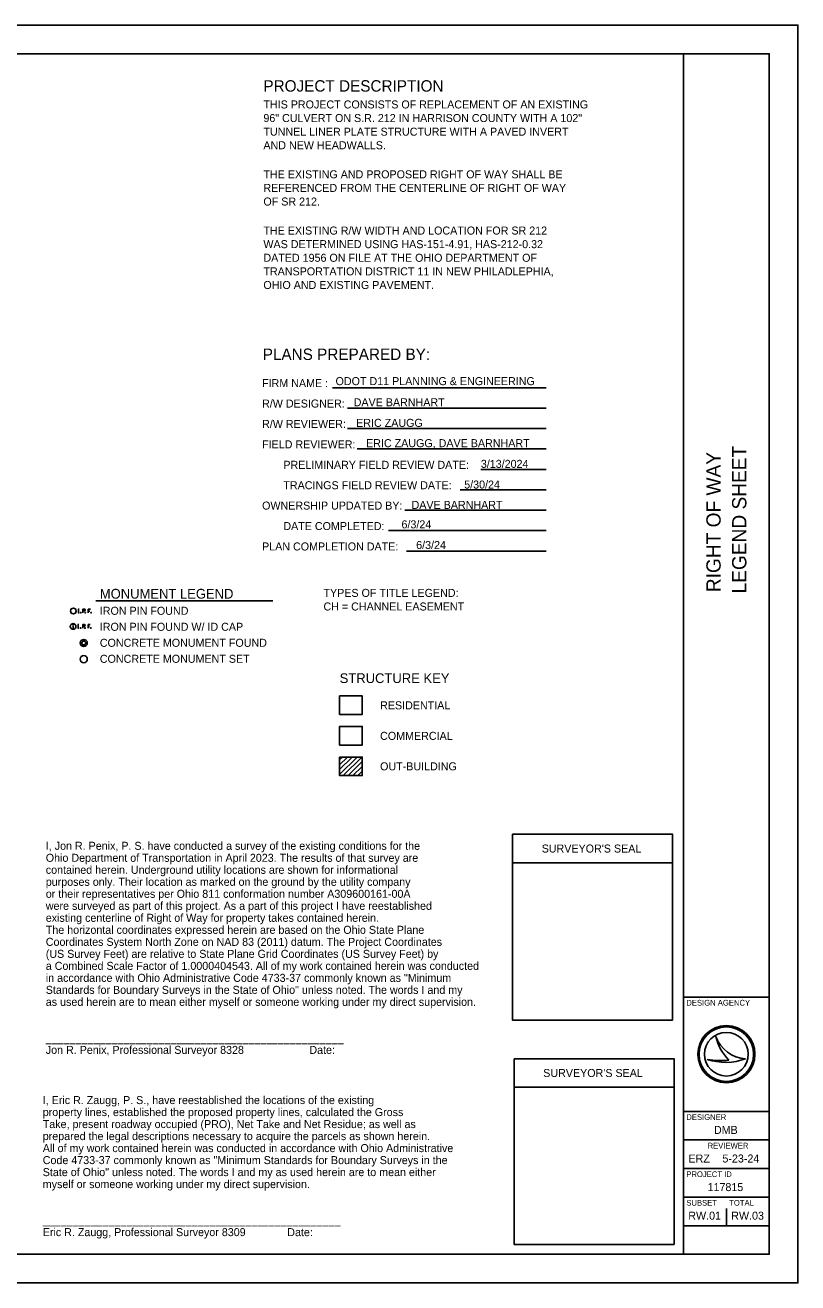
# Model space of a CAD drawing. Extents: x -1.2 to 34, y -8.5 to 22.
# Drawn here: x 20.49 to 34, y 0 to 22 of the extents above; entities that cross this region are included whole.
import ezdxf

# ---------------------------------------------------------------- set-up
doc = ezdxf.new("R2010")
doc.units = 0
for name, color, linetype in [('SC_Scratch1', 7, 'Continuous'), ('SH_Border', 7, 'Continuous'), ('SH_Cut_Line', 7, 'Continuous'), ('SH_Data', 7, 'Continuous'), ('SH_Text', 7, 'Continuous'), ('SV_X_Text', 7, 'Continuous')]:
    doc.layers.add(name, color=color, linetype=linetype)

msp = doc.modelspace()

# ---------------------------------------------------------------- linework, layer by layer
at = {"layer": 'SC_Scratch1'}
msp.add_lwpolyline([(25.985, 9.407), (26.382, 9.407), (26.382, 9.733), (25.985, 9.733)], close=True, dxfattribs=at)
at = {"layer": 'SH_Border'}
for p, q in [((32, 0.5), (32, 21.5)), ((32, 5), (33.5, 5)), ((32, 3), (33.5, 3)), ((32, 2.5), (33.5, 2.5)), ((32, 2), (33.5, 2)), ((32, 1.5), (33.5, 1.5)), ((32, 1), (33.5, 1))]:
    msp.add_line(p, q, dxfattribs=at)
msp.add_lwpolyline([(1.5, 21.5), (33.5, 21.5), (33.5, 0.5), (1.5, 0.5)], close=True, dxfattribs=at)
at = {"layer": 'SH_Cut_Line'}
msp.add_lwpolyline([(0, 0), (34, 0), (34, 22), (0, 22)], close=True, dxfattribs=at)
at = {"layer": 'SH_Data'}
for p, q in [((29.009, 7.347), (31.809, 7.347)), ((32.567, 4.31), (32.567, 4.31)), ((32.75, 4), (32.75, 4)), ((32.417, 3.91), (32.417, 3.91)), ((33.087, 3.919), (33.087, 3.919)), ((29.036, 3.421), (31.836, 3.421)), ((32.75, 1), (32.75, 1.3))]:
    msp.add_line(p, q, dxfattribs=at)
for points in [[(29.009, 7.847), (31.809, 7.847), (31.809, 4.597), (29.009, 4.597)], [(29.036, 3.921), (31.836, 3.921), (31.836, 0.671), (29.036, 0.671)]]:
    msp.add_lwpolyline(points, close=True, dxfattribs=at)
for radius in [0.5, 0.477, 0.477, 0.382]:
    msp.add_circle((32.75, 4), radius, dxfattribs=at)
for centre, radius, start, end in [((33.116, 4.498), 0.58, 198.9257, 198.9319), ((33.347, 4.47), 0.796, 191.6379, 191.6421), ((33.116, 4.498), 0.58, 198.9319, 267.1657), ((33.347, 4.47), 0.796, 191.6421, 226.0947), ((32.739, 4.87), 1.013, 251.4576, 290.0832), ((32.648, 5.154), 1.266, 259.4964, 259.4995), ((32.739, 4.87), 1.013, 251.4527, 251.4576), ((32.648, 5.154), 1.266, 259.4995, 276.6672)]:
    msp.add_arc(centre, radius, start, end, dxfattribs=at)
at = {"layer": 'SH_Text'}
for p, q in [((25.862, 15.658), (29.599, 15.658)), ((26.126, 15.301), (29.599, 15.301)), ((26.126, 14.944), (29.599, 14.944)), ((26.29, 14.587), (29.599, 14.587)), ((28.453, 14.229), (29.599, 14.229)), ((28.096, 13.872), (29.599, 13.872)), ((27.126, 13.516), (29.599, 13.516)), ((26.841, 13.158), (29.599, 13.158)), ((27.155, 12.801), (29.599, 12.801)), ((21.723, 11.931), (24.815, 11.931)), ((21.412, 11.785), (21.429, 11.785)), ((21.412, 11.785), (21.429, 11.785)), ((21.412, 11.718), (21.429, 11.718)), ((21.421, 11.718), (21.421, 11.785)), ((21.497, 11.753), (21.524, 11.753)), ((21.591, 11.718), (21.591, 11.785)), ((21.591, 11.785), (21.629, 11.785)), ((21.591, 11.752), (21.618, 11.752)), ((21.325, 11.487), (21.325, 11.45)), ((21.408, 11.516), (21.425, 11.516)), ((21.408, 11.516), (21.425, 11.516)), ((21.408, 11.449), (21.425, 11.449)), ((21.416, 11.449), (21.416, 11.516)), ((21.493, 11.484), (21.52, 11.484)), ((21.587, 11.449), (21.587, 11.516)), ((21.587, 11.516), (21.625, 11.516)), ((21.587, 11.483), (21.614, 11.483)), ((25.985, 9.196), (25.986, 9.198)), ((25.985, 9.146), (26.036, 9.198)), ((25.985, 9.061), (26.121, 9.198)), ((25.985, 8.977), (26.205, 9.198)), ((25.985, 8.892), (26.29, 9.198)), ((26.049, 8.872), (26.375, 9.198)), ((26.134, 8.872), (26.382, 9.12)), ((26.218, 8.872), (26.382, 9.035)), ((25.985, 8.876), (25.989, 8.872)), ((26.303, 8.872), (26.382, 8.95))]:
    msp.add_line(p, q, dxfattribs=at)
for points in [[(21.524, 11.785), (21.497, 11.785), (21.497, 11.718)], [(21.52, 11.516), (21.493, 11.516), (21.493, 11.449)]]:
    msp.add_lwpolyline(points, dxfattribs=at)
for points in [[(25.985, 10.268), (26.382, 10.268), (26.382, 9.942), (25.985, 9.942)], [(25.985, 9.198), (26.382, 9.198), (26.382, 8.872), (25.985, 8.872)]]:
    msp.add_lwpolyline(points, close=True, dxfattribs=at)
for centre, radius in [((21.329, 11.752), 0.05), ((21.461, 11.723), 0.00583), ((21.537, 11.723), 0.00583), ((21.639, 11.723), 0.00583), ((21.325, 11.482), 0.05), ((21.325, 11.51), 0.00667), ((21.456, 11.454), 0.00583), ((21.533, 11.454), 0.00583), ((21.635, 11.454), 0.00583), ((21.511, 11.192), 0.0625), ((21.511, 11.192), 0.0333), ((21.511, 10.91), 0.0625)]:
    msp.add_circle(centre, radius, dxfattribs=at)
for centre in [(21.522, 11.769), (21.517, 11.5)]:
    msp.add_arc(centre, 0.0162, 278.8803, 81.1197, dxfattribs=at)

# ---------------------------------------------------------------- texts
at = {"layer": 'SH_Data'}
for s, p in [('RIGHT OF WAY', (32.65, 12.082)), ('LEGEND SHEET', (33.1, 12.06))]:
    msp.add_text(s, height=0.25, rotation=90, dxfattribs=at).set_placement(p)
for s, height, p in [("SURVEYOR'S SEAL", 0.14, (29.52, 7.527)), ('DESIGN AGENCY', 0.1, (32.05, 4.85)), ("SURVEYOR'S SEAL", 0.14, (29.547, 3.601)), ('DESIGNER', 0.1, (32.05, 2.85)), ('DMB', 0.14, (32.533, 2.605)), ('REVIEWER', 0.1, (32.422, 2.35)), ('ERZ', 0.14, (32.087, 2.105)), ('5-23-24', 0.14, (32.681, 2.105)), ('PROJECT ID', 0.1, (32.05, 1.85)), ('117815', 0.14, (32.421, 1.605)), ('SUBSET', 0.1, (32.05, 1.35)), ('TOTAL', 0.1, (32.8, 1.35)), ('RW.01', 0.14, (32.084, 1.105)), ('RW.03', 0.14, (32.835, 1.105))]:
    msp.add_text(s, height=height, dxfattribs=at).set_placement(p)
at = {"layer": 'SH_Text'}
for s, height, p in [('PROJECT DESCRIPTION', 0.2, (24.653, 20.837)), ('THIS PROJECT CONSISTS OF REPLACEMENT OF AN EXISTING', 0.14, (24.653, 20.543)), ('96" CULVERT ON S.R. 212 IN HARRISON COUNTY WITH A 102"', 0.14, (24.653, 20.305)), ('TUNNEL LINER PLATE STRUCTURE WITH A PAVED INVERT', 0.14, (24.653, 20.067)), ('AND NEW HEADWALLS.', 0.14, (24.653, 19.829)), ('PLANS PREPARED BY:', 0.2, (24.641, 16.143)), ('ODOT D11 PLANNING & ENGINEERING', 0.14, (25.915, 15.703)), ('FIRM NAME :', 0.14, (24.63, 15.668)), ('R/W DESIGNER:', 0.14, (24.63, 15.311)), ('DAVE BARNHART', 0.14, (26.232, 15.333)), ('R/W REVIEWER:', 0.14, (24.63, 14.954)), ('ERIC ZAUGG', 0.14, (26.275, 14.973)), ('ERIC ZAUGG, DAVE BARNHART', 0.14, (26.449, 14.618)), ('FIELD REVIEWER:', 0.14, (24.63, 14.597)), ('PRELIMINARY FIELD REVIEW DATE:', 0.14, (25.002, 14.239)), ('3/13/2024', 0.14, (28.456, 14.256)), ('TRACINGS FIELD REVIEW DATE:', 0.14, (25.002, 13.882)), ('5/30/24', 0.14, (28.165, 13.894)), ('OWNERSHIP UPDATED BY:', 0.14, (24.63, 13.526)), ('DAVE BARNHART', 0.14, (27.244, 13.538)), ('DATE COMPLETED:', 0.14, (25.002, 13.168)), ('6/3/24', 0.14, (27.068, 13.198)), ('6/3/24', 0.14, (27.325, 12.836)), ('PLAN COMPLETION DATE:', 0.14, (24.63, 12.811)), ('MONUMENT LEGEND', 0.17, (21.792, 11.969)), ('TYPES OF TITLE LEGEND:', 0.14, (25.704, 11.999)), ('CH = CHANNEL EASEMENT', 0.14, (25.704, 11.761)), ('IRON PIN FOUND', 0.14, (21.792, 11.686)), ('IRON PIN FOUND W/ ID CAP', 0.14, (21.792, 11.406)), ('CONCRETE MONUMENT FOUND', 0.14, (21.792, 11.126)), ('CONCRETE MONUMENT SET', 0.14, (21.792, 10.846)), ('STRUCTURE KEY', 0.17, (25.987, 10.492)), ('RESIDENTIAL', 0.14, (26.694, 10.032)), ('COMMERCIAL', 0.14, (26.694, 9.498)), ('OUT-BUILDING', 0.14, (26.694, 8.965)), ('I, Jon R. Penix, P. S. have conducted a survey of the existing conditions for the', 0.14, (20.847, 7.575)), ('Ohio Department of Transportation in April 2023. The results of that survey are', 0.14, (20.847, 7.365)), ('contained herein. Underground utility locations are shown for informational', 0.14, (20.847, 7.155)), ('purposes only. Their location as marked on the ground by the utility company', 0.14, (20.847, 6.945)), ('or their representatives per Ohio 811 conformation number A309600161-00A', 0.14, (20.847, 6.735)), ('were surveyed as part of this project. As a part of this project I have reestablished', 0.14, (20.847, 6.525)), ('existing centerline of Right of Way for property takes contained herein.', 0.14, (20.847, 6.315)), ('The horizontal coordinates expressed herein are based on the Ohio State Plane', 0.14, (20.847, 6.105)), ('Coordinates System North Zone on NAD 83 (2011) datum. The Project Coordinates', 0.14, (20.847, 5.895)), ('(US Survey Feet) are relative to State Plane Grid Coordinates (US Survey Feet) by', 0.14, (20.847, 5.685)), ('a Combined Scale Factor of 1.0000404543. All of my work contained herein was conducted', 0.14, (20.847, 5.475)), ('in accordance with Ohio Administrative Code 4733-37 commonly known as "Minimum', 0.14, (20.847, 5.265)), ('Standards for Boundary Surveys in the State of Ohio" unless noted. The words I and my', 0.14, (20.847, 5.055)), ('as used herein are to mean either myself or someone working under my direct supervision.', 0.14, (20.847, 4.845)), ('__________________________________________________                                        ', 0.14, (20.847, 4.215)), ('Jon R. Penix, Professional Surveyor 8328                      Date:                  ', 0.14, (20.847, 4.005)), ('I, Eric R. Zaugg, P. S., have reestablished the locations of the existing', 0.14, (20.794, 3.127)), ('property lines, established the proposed property lines, calculated the Gross', 0.14, (20.794, 2.917)), ('Take, present roadway occupied (PRO), Net Take and Net Residue; as well as', 0.14, (20.794, 2.707)), ('prepared the legal descriptions necessary to acquire the parcels as shown herein.', 0.14, (20.794, 2.497)), ('All of my work contained herein was conducted in accordance with Ohio Administrative', 0.14, (20.794, 2.287)), ('Code 4733-37 commonly known as "Minimum Standards for Boundary Surveys in the', 0.14, (20.794, 2.077)), ('State of Ohio" unless noted. The words I and my as used herein are to mean either', 0.14, (20.794, 1.867)), ('myself or someone working under my direct supervision.', 0.14, (20.794, 1.657)), ('__________________________________________________                                        ', 0.14, (20.794, 1.027)), ('Eric R. Zaugg, Professional Surveyor 8309              Date:                  ', 0.14, (20.794, 0.817))]:
    msp.add_text(s, height=height, dxfattribs=at).set_placement(p)
at = {"layer": 'SV_X_Text'}
for s, p in [('THE EXISTING AND PROPOSED RIGHT OF WAY SHALL BE', (24.653, 19.321)), ('REFERENCED FROM THE CENTERLINE OF RIGHT OF WAY', (24.653, 19.083)), ('OF SR 212.', (24.653, 18.845)), ('THE EXISTING R/W WIDTH AND LOCATION FOR SR 212', (24.653, 18.337)), ('WAS DETERMINED USING HAS-151-4.91, HAS-212-0.32', (24.653, 18.099)), ('DATED 1956 ON FILE AT THE OHIO DEPARTMENT OF', (24.653, 17.861)), ('TRANSPORTATION DISTRICT 11 IN NEW PHILADLEPHIA,', (24.653, 17.623)), ('OHIO AND EXISTING PAVEMENT.', (24.653, 17.385))]:
    msp.add_text(s, height=0.14, dxfattribs=at).set_placement(p)

doc.saveas('drawing.dxf')
